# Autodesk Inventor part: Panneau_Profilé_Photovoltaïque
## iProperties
Created: 2009-01
Part Number: Panneau_Profilé_Photovoltaïque
Document SubType Name: Modeling
Designer: Alex_Cyril
Author: Alex_Cyril
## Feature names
1. Extrusion1
2. Perçage1 [Hole]
3. Perçage2 [Hole]
